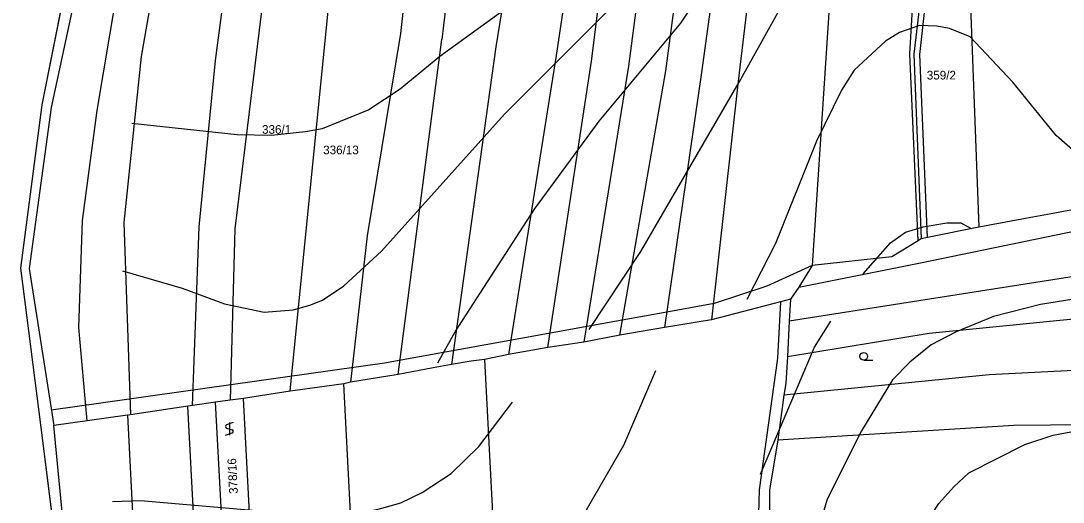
# Model space of a CAD drawing. Extents: x -555860 to -552701, y -1187050 to -1182291.
# Drawn here: x -555043.1 to -554839.8, y -1184770.2 to -1184676.2 of the extents above; entities that cross this region are included whole.
import ezdxf

# ---------------------------------------------------------------- set-up
doc = ezdxf.new("R2010")
doc.units = 0
for name, color, linetype in [('LEG_2b', 7, 'Continuous'), ('Level 25', 7, 'Continuous'), ('Level 28', 7, 'Continuous'), ('Level 30', 7, 'Continuous'), ('Level 40', 7, 'Continuous'), ('Level 41', 7, 'Continuous'), ('navrh_BV', 7, 'Continuous'), ('Poz předměty', 7, 'Continuous')]:
    doc.layers.add(name, color=color, linetype=linetype)

msp = doc.modelspace()

# ---------------------------------------------------------------- linework, layer by layer
at = {"layer": 'Level 25'}
for p, q in [((-554878.68, -1184742.47), (-554876.93, -1184742.47)), ((-555001.67, -1184754.63), (-555002.97, -1184755.1)), ((-555002.97, -1184755.71), (-555001.87, -1184756.04)), ((-555002.42, -1184754.63), (-555002.42, -1184757.13)), ((-555003.17, -1184757.13), (-555001.87, -1184756.64))]:
    msp.add_line(p, q, dxfattribs=at)
msp.add_circle((-554878.68, -1184741.72), 0.75, dxfattribs=at)
for centre, start, end in [((-555002.84, -1184755.41), 113.579, 246.421), ((-555002, -1184756.34), 293.574, 66.426)]:
    msp.add_arc(centre, 0.329, start, end, dxfattribs=at)
at = {"layer": 'Level 28'}
msp.add_lwpolyline([(-555037.85, -1184932.48), (-555034.44, -1184853.76), (-555033.83, -1184842.95), (-555035.24, -1184786.57), (-555039.16, -1184755.62), (-555043.11, -1184724.5), (-555038.96, -1184692.59), (-555032.26, -1184659), (-555018.42, -1184595.69), (-555014.13, -1184562.57), (-555013.8, -1184540.42), (-555013.62, -1184538.98), (-555013.31, -1184536.45), (-555012.91, -1184533.21), (-555012.62, -1184530.82), (-555015.32, -1184519.62), (-555021.51, -1184466.21)], dxfattribs=at)
at = {"layer": 'Level 30'}
msp.add_lwpolyline([(-555037.85, -1184932.48), (-555034.44, -1184853.76), (-555033.83, -1184842.95), (-555035.24, -1184786.57), (-555039.16, -1184755.62), (-555043.11, -1184724.5), (-555038.96, -1184692.59), (-555032.26, -1184659), (-555018.42, -1184595.69), (-555016.76, -1184582.9)], dxfattribs=at)
at = {"layer": 'Level 40'}
for points in [[(-554961.76, -1184742.97), (-554958.39, -1184736.96), (-554942.93, -1184713.01), (-554930.31, -1184695.82), (-554914.37, -1184676.68), (-554905.91, -1184663.93), (-554900.36, -1184652.28), (-554894.82, -1184635.64), (-554891.49, -1184628.29), (-554890.2, -1184626.11), (-554887.06, -1184622.97), (-554884.09, -1184620.33), (-554869.23, -1184611.94)], [(-554950.38, -1184886.82), (-554939.33, -1184884.8), (-554910.21, -1184876.76), (-554899.39, -1184872.88), (-554889.41, -1184867.89), (-554884.7, -1184864.56), (-554880.12, -1184860.26), (-554874.99, -1184853.47), (-554871.38, -1184842.52), (-554870.41, -1184836.97), (-554869.58, -1184825.88), (-554871.38, -1184798.15), (-554870.69, -1184787.05), (-554869.72, -1184781.51), (-554867.64, -1184775.96), (-554864.04, -1184770.42), (-554861.11, -1184767.2), (-554858.21, -1184764.45), (-554847.26, -1184758.91), (-554841.71, -1184757.1), (-554835.89, -1184755.99)]]:
    msp.add_lwpolyline(points, dxfattribs=at)
at = {"layer": 'Level 41'}
for points in [[(-554863.16, -1184560.36), (-554867.78, -1184563.82), (-554876.1, -1184570.61), (-554884.7, -1184581.15), (-554888.22, -1184586.01), (-554896.48, -1184599.31), (-554900.43, -1184606.47), (-554918.53, -1184641.74), (-554923.8, -1184650.48), (-554929.76, -1184658.66), (-554935.03, -1184664.06), (-554961.37, -1184683.2), (-554969.14, -1184689.58), (-554975.24, -1184693.6), (-554984.36, -1184697.32), (-554987.58, -1184697.9), (-554994.23, -1184698.59), (-555000.89, -1184698.45), (-555021.46, -1184696.28)], [(-555023.28, -1184725.01), (-555011.67, -1184728.41), (-555003.39, -1184731.45), (-554995.62, -1184733.12), (-554989.97, -1184732.63), (-554986.75, -1184731.73), (-554984.25, -1184730.76), (-554980.09, -1184727.98), (-554972.74, -1184721.19), (-554948.75, -1184694.43), (-554926.71, -1184672.38), (-554920.47, -1184664.76), (-554916.17, -1184658.38), (-554907.16, -1184642.57), (-554892.88, -1184613.73), (-554886.64, -1184604.86), (-554882.48, -1184600.28), (-554876.24, -1184594.87), (-554872.22, -1184592.38), (-554866.33, -1184590.57)], [(-554932.26, -1184736.49), (-554922.19, -1184721.24), (-554903, -1184688.19), (-554881.78, -1184650.06), (-554872.63, -1184636.19), (-554871.95, -1184635.62)], [(-554829.37, -1184708.95), (-554841.16, -1184698.59), (-554849.61, -1184688.19), (-554857.93, -1184679.32), (-554861.96, -1184677.68), (-554864.45, -1184677.24), (-554867.78, -1184677.1), (-554871.69, -1184678.51), (-554874.44, -1184680.15), (-554880.54, -1184685.83), (-554883.03, -1184689.72), (-554887.88, -1184699.7), (-554895.93, -1184719.67), (-554901.47, -1184730.62)], [(-554878.81, -1184725.62), (-554873.46, -1184719.53), (-554870.55, -1184717.45), (-554867.07, -1184716.46), (-554862.51, -1184715.64), (-554859.74, -1184715.64), (-554857.74, -1184716.73)], [(-554838.11, -1184730.62), (-554844.21, -1184731.59), (-554853.36, -1184733.95), (-554860.64, -1184736.92), (-554865.56, -1184739.49), (-554869.71, -1184742.86), (-554873.05, -1184746.29), (-554879.15, -1184756.27), (-554885.8, -1184769.58), (-554889.66, -1184782.71), (-554892.82, -1184795.39)], [(-554898.82, -1184764.69), (-554888.3, -1184739.91), (-554885.1, -1184734.86)], [(-555037.83, -1184795.95), (-555021.27, -1184796.34), (-555000.5, -1184799.05), (-554991.43, -1184801.2), (-554984.53, -1184803.41), (-554979.05, -1184804.82), (-554974.82, -1184805.63), (-554971.13, -1184805.65), (-554965.95, -1184805.22), (-554961.89, -1184804), (-554958.46, -1184802.58), (-554950, -1184796.07), (-554944.32, -1184790.1), (-554935.72, -1184776.79), (-554925.46, -1184759.04), (-554919.22, -1184744.49)], [(-555025.22, -1184770.06), (-555019.75, -1184769.86), (-554985.92, -1184772.77), (-554977.59, -1184772.49), (-554973.16, -1184771.52), (-554968.99, -1184770.34), (-554964.84, -1184768.33), (-554959.15, -1184764.59), (-554953.75, -1184759.32), (-554947.19, -1184750.69)]]:
    msp.add_lwpolyline(points, dxfattribs=at)
at = {"layer": 'navrh_BV'}
for p, q in [((-555004.49, -1184596.54), (-555019.64, -1184683.15)), ((-555005.15, -1184683.97), (-554993.72, -1184597.17)), ((-554881.28, -1184610.08), (-554888.73, -1184723.98)), ((-554956.75, -1184645.44), (-554961.01, -1184679.86)), ((-554944.65, -1184645.78), (-554950.48, -1184681.28)), ((-554933.31, -1184646.24), (-554938.67, -1184683)), ((-554931.82, -1184684.05), (-554927.06, -1184646.38)), ((-554919.55, -1184646.72), (-554924.58, -1184685.06)), ((-554917.29, -1184685.96), (-554912.09, -1184646.81)), ((-554904.93, -1184647.06), (-554910.39, -1184686.74)), ((-554898.39, -1184647.15), (-554903.17, -1184688.01)), ((-554993.54, -1184653.05), (-555001.37, -1184716.84)), ((-554990.57, -1184748.5), (-554981.18, -1184654.42)), ((-554966.57, -1184656.03), (-554969.07, -1184678.71)), ((-554869.72, -1184682.65), (-554868.18, -1184658.19)), ((-555038.96, -1184692.59), (-555032.26, -1184659)), ((-555030.02, -1184659.42), (-555037.18, -1184693.13)), ((-555028.25, -1184693.74), (-555022.54, -1184660)), ((-554866.17, -1184658.51), (-554868.89, -1184682.71)), ((-554867.73, -1184682.78), (-554865.2, -1184658.98)), ((-554858.41, -1184660.05), (-554856.21, -1184716.49)), ((-554969.07, -1184678.71), (-554975.58, -1184718.16)), ((-554969.53, -1184745.26), (-554961.01, -1184679.86)), ((-554950.48, -1184681.28), (-554959.1, -1184743.34)), ((-555019.64, -1184683.15), (-555023.03, -1184715.55)), ((-555008.34, -1184716.42), (-555005.15, -1184683.97)), ((-554938.67, -1184683), (-554948.01, -1184741.34)), ((-554940.32, -1184739.96), (-554931.82, -1184684.05)), ((-554868.1, -1184719.17), (-554869.72, -1184682.65)), ((-554868.89, -1184682.71), (-554867.48, -1184718.75)), ((-554866.23, -1184718.52), (-554867.73, -1184682.78)), ((-554924.58, -1184685.06), (-554933.28, -1184738.92)), ((-554926.29, -1184737.58), (-554917.29, -1184685.96)), ((-554910.39, -1184686.74), (-554917.56, -1184736.06)), ((-554903.17, -1184688.01), (-554908.36, -1184734.59)), ((-555043.11, -1184724.5), (-555038.96, -1184692.59)), ((-555037.18, -1184693.13), (-555041.51, -1184724.58)), ((-555031.1, -1184715.21), (-555028.25, -1184693.74)), ((-554835.19, -1184712.6), (-554842.1, -1184713.87)), ((-554867.64, -1184723.45), (-554824.23, -1184714.52)), ((-554847.14, -1184714.82), (-554856.21, -1184716.49)), ((-554842.1, -1184713.87), (-554847.14, -1184714.82)), ((-555031.77, -1184736.06), (-555031.1, -1184715.21)), ((-555023.03, -1184715.55), (-555021.75, -1184753.12)), ((-555009.6, -1184751.29), (-555008.34, -1184716.42)), ((-555001.37, -1184716.84), (-555002.31, -1184750.25)), ((-554856.21, -1184716.49), (-554866.23, -1184718.52)), ((-554975.58, -1184718.16), (-554978.82, -1184746.76)), ((-554868.1, -1184719.17), (-554873.22, -1184722.29)), ((-554867.48, -1184718.75), (-554868.1, -1184719.17)), ((-554866.23, -1184718.52), (-554867.48, -1184718.75)), ((-554873.22, -1184722.29), (-554888.73, -1184723.98)), ((-555039.16, -1184755.62), (-555043.11, -1184724.5)), ((-555041.51, -1184724.58), (-555036.69, -1184755.24)), ((-554821.26, -1184723.51), (-554893.23, -1184734.84)), ((-554891.35, -1184728.22), (-554867.64, -1184723.45)), ((-554888.73, -1184723.98), (-554891.35, -1184728.22)), ((-554891.35, -1184728.22), (-554893, -1184730.57)), ((-554894.93, -1184731.08), (-554908.36, -1184734.59)), ((-554894.93, -1184731.08), (-554895.53, -1184742.06)), ((-554893, -1184730.57), (-554894.93, -1184731.08)), ((-554893, -1184730.57), (-554893.23, -1184734.84)), ((-554865.93, -1184737.22), (-554818.51, -1184732.43)), ((-554908.36, -1184734.59), (-554917.56, -1184736.06)), ((-554893.23, -1184734.84), (-554893.56, -1184741.74)), ((-555030.18, -1184754.28), (-555031.77, -1184736.06)), ((-554917.56, -1184736.06), (-554926.29, -1184737.58)), ((-554893.56, -1184741.74), (-554865.93, -1184737.22)), ((-554933.28, -1184738.92), (-554940.32, -1184739.96)), ((-554926.29, -1184737.58), (-554933.28, -1184738.92)), ((-554948.01, -1184741.34), (-554952.68, -1184742.31)), ((-554940.32, -1184739.96), (-554948.01, -1184741.34)), ((-554959.1, -1184743.34), (-554962.65, -1184743.97)), ((-554955.29, -1184742.67), (-554959.1, -1184743.34)), ((-554952.68, -1184742.31), (-554955.29, -1184742.67)), ((-554952.68, -1184742.31), (-554944.38, -1184898.49)), ((-554895.53, -1184742.06), (-554899.06, -1184767.81)), ((-554893.56, -1184741.74), (-554893.91, -1184747.05)), ((-554814.88, -1184743.32), (-554854.23, -1184745.33)), ((-554969.53, -1184745.26), (-554978.82, -1184746.76)), ((-554962.65, -1184743.97), (-554969.53, -1184745.26)), ((-554854.23, -1184745.33), (-554894.25, -1184749.3)), ((-554980.08, -1184747.09), (-554989.63, -1184748.41)), ((-554978.82, -1184746.76), (-554980.08, -1184747.09)), ((-554973.37, -1184879.16), (-554980.08, -1184747.09)), ((-554893.91, -1184747.05), (-554894.25, -1184749.3)), ((-554990.57, -1184748.5), (-554999.71, -1184749.95)), ((-554989.63, -1184748.41), (-554990.57, -1184748.5)), ((-554894.25, -1184749.3), (-554895.43, -1184758.04)), ((-555010.55, -1184751.45), (-555021.75, -1184753.12)), ((-555009.6, -1184751.29), (-555010.55, -1184751.45)), ((-555007.58, -1184808.37), (-555010.55, -1184751.45)), ((-555005.11, -1184750.65), (-555009.6, -1184751.29)), ((-555002.31, -1184750.25), (-555005.11, -1184750.65)), ((-555002.02, -1184808.17), (-555005.11, -1184750.65)), ((-554999.71, -1184749.95), (-555002.31, -1184750.25)), ((-554996.66, -1184807.98), (-554999.71, -1184749.95)), ((-555022.31, -1184753.2), (-555030.18, -1184754.28)), ((-555021.75, -1184753.12), (-555022.31, -1184753.2)), ((-555022.31, -1184753.2), (-555017.2, -1184850.85)), ((-555035.24, -1184786.57), (-555039.16, -1184755.62)), ((-555030.18, -1184754.28), (-555036.69, -1184755.24)), ((-555033.56, -1184786.91), (-555036.69, -1184755.24)), ((-554895.43, -1184758.04), (-554849.41, -1184755.14)), ((-554849.41, -1184755.14), (-554775.16, -1184754.66)), ((-554895.43, -1184758.04), (-554897.04, -1184767.82)), ((-554899.06, -1184767.81), (-554900.96, -1184835.23)), ((-554897.04, -1184767.82), (-554897.06, -1184772.33))]:
    msp.add_line(p, q, dxfattribs=at)
at = {"layer": 'Poz předměty'}
msp.add_lwpolyline([(-554888.73, -1184723.98), (-554897.56, -1184728.03), (-554907.89, -1184731.4), (-554917.12, -1184733.07), (-554925.78, -1184734.63), (-554972.2, -1184743.03), (-555037.17, -1184752.21)], dxfattribs=at)

# ---------------------------------------------------------------- texts
at = {"layer": 'LEG_2b'}
for s, p in [('359/2', (-554866.39, -1184687.66)), ('336/1', (-554996.06, -1184698.26)), ('336/13', (-554984.14, -1184702.27))]:
    msp.add_text(s, height=1.7, dxfattribs=at).set_placement(p)
msp.add_text('378/16', height=1.7, rotation=93, dxfattribs=at).set_placement((-555000.77, -1184768.52))

doc.saveas('drawing.dxf')
